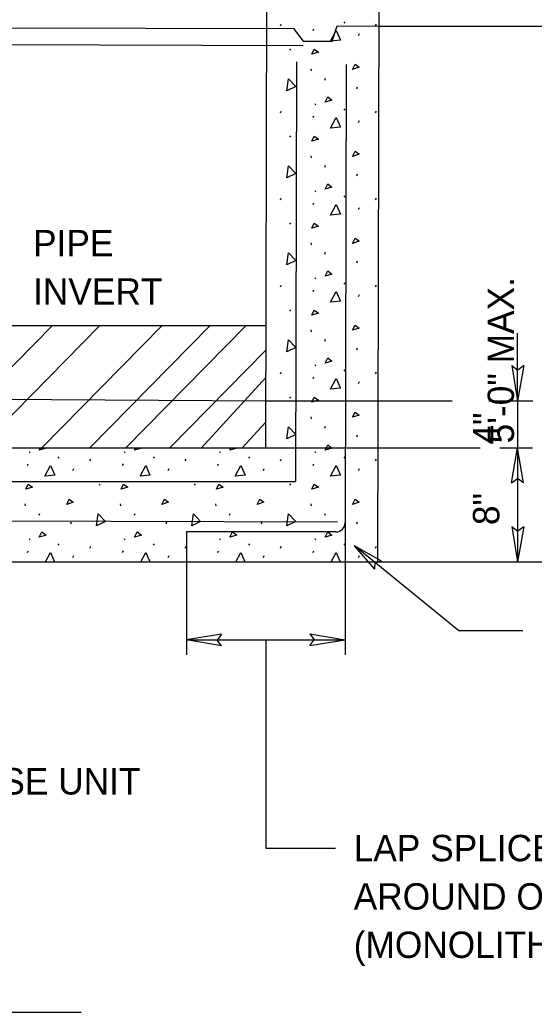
# Model space of a CAD drawing. Extents: x 4.74 to 11.91, y -5.26 to 4.54.
# Drawn here: x 7.798 to 8.968, y -2.334 to -0.077 of the extents above; entities that cross this region are included whole.
import ezdxf

# ---------------------------------------------------------------- set-up
doc = ezdxf.new("R2010")
doc.units = 0
for name, color, linetype in [('DETL-DIMS', 7, 'Continuous'), ('DETL-LINE', 7, 'Continuous'), ('DETL-NOTE', 7, 'Continuous'), ('DETL-PATT', 7, 'Continuous'), ('DETL-TITL', 7, 'Continuous')]:
    doc.layers.add(name, color=color, linetype=linetype)

msp = doc.modelspace()

# ---------------------------------------------------------------- linework, layer by layer
at = {"layer": 'DETL-DIMS'}
for p, q in [((8.6152, -0.091), (9.1105, -0.091)), ((8.9302, -0.9435), (8.9302, -0.7899)), ((8.9173, -0.8634), (8.9302, -0.9435)), ((8.9173, -0.8634), (8.9306, -0.8735)), ((8.944, -0.8635), (8.9302, -0.9435)), ((8.944, -0.8635), (8.9306, -0.8735)), ((8.3574, -0.9435), (8.7811, -0.9435)), ((8.8645, -0.9435), (8.9645, -0.9435)), ((8.9302, -0.9435), (8.9302, -1.0502)), ((8.3571, -1.0502), (8.8448, -1.0502)), ((8.8896, -1.0502), (8.9642, -1.0502)), ((8.9164, -1.1301), (8.9302, -1.0502)), ((8.9302, -1.0502), (8.9302, -1.3098)), ((8.9431, -1.1303), (8.9302, -1.0502)), ((8.9164, -1.1301), (8.9298, -1.1202)), ((8.9431, -1.1303), (8.9298, -1.1202)), ((8.5377, -1.2209), (8.5377, -1.521)), ((8.9173, -1.2297), (8.9302, -1.3098)), ((8.9173, -1.2297), (8.9306, -1.2398)), ((8.944, -1.2299), (8.9302, -1.3098)), ((8.944, -1.2299), (8.9306, -1.2398)), ((8.1767, -1.2417), (8.1767, -1.521)), ((8.7962, -1.467), (8.5588, -1.2733)), ((8.6057, -1.3266), (8.5588, -1.2733)), ((8.6205, -1.3085), (8.5588, -1.2733)), ((8.6205, -1.3085), (8.6063, -1.312)), ((8.6057, -1.3266), (8.6063, -1.312)), ((8.612, -1.3098), (9.572, -1.3098)), ((8.9416, -1.467), (8.7962, -1.467)), ((8.2568, -1.4745), (8.1767, -1.4874)), ((8.1767, -1.4874), (8.5377, -1.4874)), ((8.2566, -1.5012), (8.1767, -1.4874)), ((8.2568, -1.4745), (8.2467, -1.4878)), ((8.2566, -1.5012), (8.2467, -1.4878)), ((8.3572, -1.4874), (8.3572, -1.9609)), ((8.4576, -1.5002), (8.4677, -1.487)), ((8.4576, -1.5002), (8.5377, -1.4874)), ((8.4578, -1.4736), (8.5377, -1.4874)), ((8.4578, -1.4736), (8.4677, -1.487)), ((8.3572, -1.9609), (8.5157, -1.9609))]:
    msp.add_line(p, q, dxfattribs=at)
at = {"layer": 'DETL-LINE'}
for p, q in [((8.3571, -1.0502), (8.3613, 0.5341)), ((8.612, -1.3098), (8.6169, 0.5315)), ((6.2659, -0.0908), (8.4204, -0.0965)), ((8.4204, -0.0965), (8.4422, -0.1251)), ((8.508, -0.1253), (8.5199, -0.0908)), ((8.5199, -0.0908), (8.6152, -0.091)), ((6.253, -0.1293), (8.4421, -0.1351)), ((8.4422, -0.1251), (8.508, -0.1253)), ((8.4275, -0.1721), (8.425, -1.1267)), ((8.5405, -0.1784), (8.5377, -1.2209)), ((8.3579, -0.7729), (6.3432, -0.7729)), ((6.3428, -0.9314), (8.3574, -0.9435)), ((6.3425, -1.0502), (8.3571, -1.0502)), ((6.2769, -1.1267), (8.425, -1.1267)), ((6.1881, -1.2125), (8.5207, -1.2187)), ((8.5169, -1.2417), (8.1767, -1.2417)), ((6.0977, -1.3098), (8.612, -1.3098))]:
    msp.add_line(p, q, dxfattribs=at)
msp.add_arc((8.5169, -1.2209), 0.0208, 270, 359.8473, dxfattribs=at)
at = {"layer": 'DETL-PATT'}
for p, q in [((8.3905, -0.0909), (8.3926, -0.0866)), ((8.5347, -0.0817), (8.5368, -0.0844)), ((8.6072, -0.0909), (8.6093, -0.0866)), ((8.4651, -0.1014), (8.4667, -0.0972)), ((8.5685, -0.1122), (8.5707, -0.1079)), ((8.4114, -0.1428), (8.4136, -0.146)), ((8.4597, -0.1884), (8.4603, -0.1927)), ((8.4918, -0.2142), (8.4934, -0.2099)), ((8.5642, -0.2335), (8.5658, -0.2292)), ((8.4689, -0.2673), (8.4705, -0.27)), ((8.3905, -0.2888), (8.3926, -0.2845)), ((8.5347, -0.2797), (8.5368, -0.2823)), ((8.6072, -0.2888), (8.6093, -0.2845)), ((8.4651, -0.2994), (8.4667, -0.2951)), ((8.5685, -0.3101), (8.5707, -0.3058)), ((8.4114, -0.3407), (8.4136, -0.3439)), ((8.4597, -0.3863), (8.4603, -0.3906)), ((8.4918, -0.4121), (8.4934, -0.4078)), ((8.5642, -0.4314), (8.5658, -0.4271)), ((8.4689, -0.4652), (8.4705, -0.4679)), ((8.3905, -0.4867), (8.3926, -0.4824)), ((8.4651, -0.4973), (8.4667, -0.493)), ((8.5347, -0.4776), (8.5368, -0.4803)), ((8.6072, -0.4867), (8.6093, -0.4824)), ((8.5685, -0.508), (8.5707, -0.5037)), ((8.4114, -0.5386), (8.4136, -0.5418)), ((8.4597, -0.5842), (8.4603, -0.5885)), ((8.4918, -0.61), (8.4934, -0.6057)), ((8.5642, -0.6293), (8.5658, -0.625)), ((8.4689, -0.6631), (8.4705, -0.6658)), ((8.5347, -0.6755), (8.5368, -0.6782)), ((8.3905, -0.6846), (8.3926, -0.6803)), ((8.4651, -0.6952), (8.4667, -0.6909)), ((8.6072, -0.6846), (8.6093, -0.6803)), ((8.5685, -0.7059), (8.5707, -0.7016)), ((8.4114, -0.7365), (8.4136, -0.7398)), ((7.5988, -1.0502), (7.8718, -0.7729)), ((7.7064, -1.0502), (7.9795, -0.7729)), ((7.8481, -1.0502), (8.1211, -0.7729)), ((7.9573, -1.0502), (8.2303, -0.7729)), ((8.0392, -1.0502), (8.3123, -0.7729)), ((8.4597, -0.7822), (8.4603, -0.7864)), ((8.4918, -0.8079), (8.4934, -0.8036)), ((8.139, -1.0502), (8.3577, -0.828)), ((8.5642, -0.8272), (8.5658, -0.8229)), ((8.3905, -0.8825), (8.3926, -0.8782)), ((8.4689, -0.8611), (8.4705, -0.8637)), ((8.5347, -0.8734), (8.5368, -0.8761)), ((8.6072, -0.8825), (8.6093, -0.8782)), ((8.2111, -1.0502), (8.3575, -0.8905)), ((8.4651, -0.8931), (8.4667, -0.8888)), ((8.5685, -0.9039), (8.5707, -0.8996)), ((8.4114, -0.9344), (8.4136, -0.9377)), ((8.3037, -1.0502), (8.3573, -0.9918)), ((8.4597, -0.9801), (8.4603, -0.9844)), ((8.4918, -1.0058), (8.4934, -1.0015)), ((8.5642, -1.0252), (8.5658, -1.0209)), ((7.8189, -1.059), (7.8205, -1.0617)), ((8.0355, -1.059), (8.0371, -1.0617)), ((8.2522, -1.059), (8.2538, -1.0617)), ((8.4689, -1.059), (8.4705, -1.0617)), ((7.8847, -1.0713), (7.8868, -1.074)), ((7.9572, -1.0804), (7.9593, -1.0762)), ((8.1014, -1.0713), (8.1035, -1.074)), ((8.1738, -1.0804), (8.176, -1.0762)), ((8.318, -1.0713), (8.3202, -1.074)), ((8.3905, -1.0804), (8.3926, -1.0762)), ((8.5347, -1.0713), (8.5368, -1.074)), ((8.6072, -1.0804), (8.6093, -1.0762)), ((7.8151, -1.091), (7.8167, -1.0867)), ((7.9185, -1.1018), (7.9207, -1.0975)), ((8.0318, -1.091), (8.0334, -1.0867)), ((8.1352, -1.1018), (8.1373, -1.0975)), ((8.2484, -1.091), (8.25, -1.0867)), ((8.3518, -1.1018), (8.354, -1.0975)), ((8.4651, -1.091), (8.4667, -1.0867)), ((8.5685, -1.1018), (8.5707, -1.0975)), ((7.9781, -1.1324), (7.9802, -1.1356)), ((8.1948, -1.1324), (8.1969, -1.1356)), ((8.4114, -1.1324), (8.4136, -1.1356)), ((7.8097, -1.178), (7.8103, -1.1823)), ((8.0264, -1.178), (8.0269, -1.1823)), ((8.2431, -1.178), (8.2436, -1.1823)), ((8.4597, -1.178), (8.4603, -1.1823)), ((7.8418, -1.2038), (7.8434, -1.1995)), ((7.9142, -1.2231), (7.9158, -1.2188)), ((8.0584, -1.2038), (8.06, -1.1995)), ((8.1309, -1.2231), (8.1325, -1.2188)), ((8.2751, -1.2038), (8.2767, -1.1995)), ((8.3475, -1.2231), (8.3492, -1.2188)), ((8.4918, -1.2038), (8.4934, -1.1995)), ((8.5642, -1.2231), (8.5658, -1.2188)), ((7.8189, -1.2569), (7.8205, -1.2596)), ((8.0355, -1.2569), (8.0371, -1.2596)), ((8.2522, -1.2569), (8.2538, -1.2596)), ((8.4689, -1.2569), (8.4705, -1.2596)), ((7.8151, -1.2889), (7.8167, -1.2847)), ((7.8847, -1.2692), (7.8868, -1.2719)), ((7.9572, -1.2784), (7.9593, -1.2741)), ((8.0318, -1.2889), (8.0334, -1.2847)), ((8.1014, -1.2692), (8.1035, -1.2719)), ((8.1738, -1.2784), (8.176, -1.2741)), ((8.2484, -1.2889), (8.25, -1.2847)), ((8.318, -1.2692), (8.3202, -1.2719)), ((8.3905, -1.2784), (8.3926, -1.2741)), ((8.4651, -1.2889), (8.4667, -1.2847)), ((8.5347, -1.2692), (8.5368, -1.2719)), ((8.6072, -1.2784), (8.6093, -1.2741)), ((7.9185, -1.2997), (7.9207, -1.2954)), ((8.1352, -1.2997), (8.1373, -1.2954)), ((8.3518, -1.2997), (8.354, -1.2954)), ((8.5685, -1.2997), (8.5707, -1.2954))]:
    msp.add_line(p, q, dxfattribs=at)
for points in [[(8.5046, -0.1251), (8.5175, -0.1009), (8.5272, -0.1235), (8.5046, -0.1251)], [(8.4619, -0.1551), (8.4672, -0.1433), (8.4769, -0.1503), (8.4619, -0.1551)], [(8.5546, -0.1895), (8.5605, -0.1777), (8.5696, -0.1846), (8.5546, -0.1895)], [(8.4055, -0.2383), (8.4093, -0.2109), (8.4259, -0.2287), (8.4055, -0.2383)], [(8.4923, -0.2641), (8.4982, -0.2523), (8.5079, -0.2593), (8.4923, -0.2641)], [(8.5046, -0.323), (8.5175, -0.2988), (8.5272, -0.3214), (8.5046, -0.323)], [(8.4619, -0.353), (8.4672, -0.3412), (8.4769, -0.3482), (8.4619, -0.353)], [(8.5546, -0.3874), (8.5605, -0.3756), (8.5696, -0.3826), (8.5546, -0.3874)], [(8.4055, -0.4362), (8.4093, -0.4089), (8.4259, -0.4266), (8.4055, -0.4362)], [(8.4923, -0.462), (8.4982, -0.4502), (8.5079, -0.4572), (8.4923, -0.462)], [(8.5046, -0.5209), (8.5175, -0.4967), (8.5272, -0.5193), (8.5046, -0.5209)], [(8.4619, -0.551), (8.4672, -0.5391), (8.4769, -0.5461), (8.4619, -0.551)], [(8.5546, -0.5853), (8.5605, -0.5735), (8.5696, -0.5805), (8.5546, -0.5853)], [(8.4055, -0.6342), (8.4093, -0.6068), (8.4259, -0.6245), (8.4055, -0.6342)], [(8.4923, -0.6599), (8.4982, -0.6481), (8.5079, -0.6551), (8.4923, -0.6599)], [(8.5046, -0.7188), (8.5175, -0.6947), (8.5272, -0.7172), (8.5046, -0.7188)], [(8.4619, -0.7489), (8.4672, -0.7371), (8.4769, -0.744), (8.4619, -0.7489)], [(8.5546, -0.7832), (8.5605, -0.7714), (8.5696, -0.7784), (8.5546, -0.7832)], [(8.4055, -0.8321), (8.4093, -0.8047), (8.4259, -0.8224), (8.4055, -0.8321)], [(8.4923, -0.8578), (8.4982, -0.846), (8.5079, -0.853), (8.4923, -0.8578)], [(8.5046, -0.9167), (8.5175, -0.8926), (8.5272, -0.9151), (8.5046, -0.9167)], [(8.4619, -0.9468), (8.4672, -0.935), (8.4769, -0.942), (8.4619, -0.9468)], [(8.5546, -0.9811), (8.5605, -0.9693), (8.5696, -0.9763), (8.5546, -0.9811)], [(8.4055, -1.03), (8.4093, -1.0026), (8.4259, -1.0203), (8.4055, -1.03)], [(7.8423, -1.0558), (7.8451, -1.0502)], [(7.8569, -1.0502), (7.8579, -1.0509), (7.8423, -1.0558)], [(8.059, -1.0558), (8.0617, -1.0502)], [(8.0735, -1.0502), (8.0745, -1.0509), (8.059, -1.0558)], [(8.2756, -1.0558), (8.2784, -1.0502)], [(8.2902, -1.0502), (8.2912, -1.0509), (8.2756, -1.0558)], [(8.4923, -1.0558), (8.4982, -1.0439), (8.5079, -1.0509), (8.4923, -1.0558)], [(7.8546, -1.1146), (7.8675, -1.0905), (7.8772, -1.113), (7.8546, -1.1146)], [(8.0713, -1.1146), (8.0842, -1.0905), (8.0938, -1.113), (8.0713, -1.1146)], [(8.288, -1.1146), (8.3009, -1.0905), (8.3105, -1.113), (8.288, -1.1146)], [(8.5046, -1.1146), (8.5175, -1.0905), (8.5272, -1.113), (8.5046, -1.1146)], [(7.8119, -1.1447), (7.8172, -1.1329), (7.8269, -1.1399), (7.8119, -1.1447)], [(8.0285, -1.1447), (8.0339, -1.1329), (8.0436, -1.1399), (8.0285, -1.1447)], [(8.2452, -1.1447), (8.2506, -1.1329), (8.2602, -1.1399), (8.2452, -1.1447)], [(8.4619, -1.1447), (8.4672, -1.1329), (8.4769, -1.1399), (8.4619, -1.1447)], [(7.9046, -1.1791), (7.9105, -1.1673), (7.9196, -1.1742), (7.9046, -1.1791)], [(8.1212, -1.1791), (8.1271, -1.1673), (8.1362, -1.1742), (8.1212, -1.1791)], [(8.3379, -1.1791), (8.3438, -1.1673), (8.3529, -1.1742), (8.3379, -1.1791)], [(8.5546, -1.1791), (8.5605, -1.1673), (8.5696, -1.1742), (8.5546, -1.1791)], [(7.9722, -1.2279), (7.9759, -1.2005), (7.9926, -1.2182), (7.9722, -1.2279)], [(8.1889, -1.2279), (8.1926, -1.2005), (8.2092, -1.2182), (8.1889, -1.2279)], [(8.4055, -1.2279), (8.4093, -1.2005), (8.4259, -1.2182), (8.4055, -1.2279)], [(7.8423, -1.2537), (7.8482, -1.2419), (7.8579, -1.2488), (7.8423, -1.2537)], [(8.059, -1.2537), (8.0649, -1.2419), (8.0745, -1.2488), (8.059, -1.2537)], [(8.2756, -1.2537), (8.2815, -1.2419), (8.2912, -1.2488), (8.2756, -1.2537)], [(8.4923, -1.2537), (8.4982, -1.2419), (8.5079, -1.2488), (8.4923, -1.2537)], [(7.8561, -1.3098), (7.8675, -1.2884), (7.8767, -1.3098)], [(8.0728, -1.3098), (8.0842, -1.2884), (8.0933, -1.3098)], [(8.2894, -1.3098), (8.3009, -1.2884), (8.31, -1.3098)], [(8.5061, -1.3098), (8.5175, -1.2884), (8.5267, -1.3098)]]:
    msp.add_lwpolyline(points, dxfattribs=at)
at = {"layer": 'DETL-TITL'}
msp.add_line((6.8885, -2.3342), (7.9378, -2.3342), dxfattribs=at)

# ---------------------------------------------------------------- texts
at = {"layer": 'DETL-NOTE'}
for s, p in [('PIPE', (7.828, -0.6148)), ('INVERT', (7.828, -0.7248)), ('BOTTOM OF BASE UNIT', (7.1496, -1.8391)), ('LAP SPLICE REINFORCEMENT 1\'-0" (TYP.)', (8.5573, -1.9909)), ('AROUND OUTSIDE CORNERS AS SHOWN', (8.5573, -2.1009)), ('(MONOLITHIC BASE ONLY)', (8.5573, -2.2109))]:
    msp.add_text(s, height=0.06, dxfattribs=at).set_placement(p)
for s, p in [('        5\'-0" MAX.', (8.9218, -1.2187)), ('4"', (8.8885, -1.0432)), ('8"', (8.8885, -1.2263))]:
    msp.add_text(s, height=0.06, rotation=90, dxfattribs=at).set_placement(p)

doc.saveas('drawing.dxf')
